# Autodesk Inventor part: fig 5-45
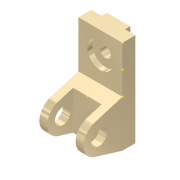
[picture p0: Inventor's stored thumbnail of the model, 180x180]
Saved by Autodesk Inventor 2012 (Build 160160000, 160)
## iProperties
Shininess: 65.0
Angle Display Precision: 2
Document Length Units: 11269
Document Angle Units: 11279
Document Time Units: 11290
Document Mass Units: 11283
Document Length Units Precision: 3
Document Angle Units Precision: 2
Created: 2001-11
Part Number: fig 5-45
Document SubType Name: Modeling
Designer: Renu Muthoo
Density: 1 g/cm^3
Material: Default
Density: 0.0
Volumn: 0.0
Area: 0.0
PropertySet Name: Model Information
Control State: 0
Master: False
Checked Out: False
Author: Renu Muthoo
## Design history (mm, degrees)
node "Sketch1"
sketch "Sketch2"
  geometry: L1 (33.257, 104.664)-(33.257, -75.336); L2 (33.257, -75.336)-(8.257, -75.336); L3 (8.257, -75.336)-(-45.451, -59.045); L4 (-45.451, -1.628)-(8.257, 14.664); L5 (8.257, 14.664)-(8.257, 104.664); L6 (8.257, 104.664)-(33.257, 104.664); C1 r 15 at (-36.743, -30.336); A1 r 30 centre (-36.743, -30.336) between (-45.451, -1.628) and (-45.451, -59.045)
  constraints: 12 end point, 2 centre point, 2 equal length, 2 parallel, 2 point on circle, 2 tangent, 1 coincident, 1 perpendicular, 1 vertical
  dimensions: "d0" = 180 distance of L1.start L1.end; "d1" = 30 radius of A1; "d2" = 25 distance of L5.end L1.start; "d3" = 45 distance from line of L2 A1.centre; "d4" = 70 distance from line of L1 A1.centre; "d5" = 30 diameter of C1
extrude "Extrusion1" new body sketch "Sketch2" distance "d6" = 85; taper "d7" = 0 deg
workplane "Work Plane1"
sketch "Sketch3"
  geometry: L1 (15, 62.364)-(70, 62.364); L2 (70, 62.364)-(70, -52.386); L3 (70, -52.386)-(15, -52.386); L4 (15, -52.386)-(15, 62.364); L5 (0, -45)-(0, -28.708) reference
  constraints: 8 end point, 2 parallel, 1 horizontal, 1 perpendicular
  dimensions: "d8" = 55 distance of L1.start L1.end; "d9" = 15 distance between parallel lines of L5 L4
extrude "Extrusion2" cut sketch "Sketch3" distance "d10" = 50; taper "d11" = 0 deg
sketch "Sketch4"
  geometry: L1 (0, 25)-(85, 25) reference; L2 (0, 0)-(0, 25) reference; L3 (20, 25)-(65, 25); L4 (65, 25)-(65, 35); L5 (65, 35)-(20, 35); L6 (20, 35)-(20, 25)
  constraints: 8 end point, 2 parallel, 1 horizontal, 1 perpendicular, 1 point on line
  dimensions: "d12" = 45 distance of L4.end L5.end; "d13" = 10 distance of L3.end L4.end; "d14" = 20 distance between parallel lines of L2 L6
extrude "Extrusion3" join sketch "Sketch4" stored distance "d15" = 50; taper "d16" = 0 deg
sketch "Sketch5"
  geometry: L1 (85, 0)-(85, 90) reference; L2 (0, 90)-(85, 90) reference; 1 further point
  dimensions: "d17" = 42 distance from line of L2 point (42.5, 48); "d18" = 42.5 distance from line of L1 point (42.5, 48)
hole "Hole1" sketch "Sketch5" at (42.5, 48) diameter "d19" = 20; stored, may be unused: countersink angle "d23" = 82 deg, drill point angle "d25" = 118 deg; dims "d20" = 6, "d21" = 50, "d22" = 10, "d24" = 8
workpoint "Work Point1"
workpoint "Work Point2"
workpoint "Work Point3"
workpoint "Work Point4"
workpoint "Work Point5"
body "Solid1"
